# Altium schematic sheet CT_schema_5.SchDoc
size 255 x 245 mm
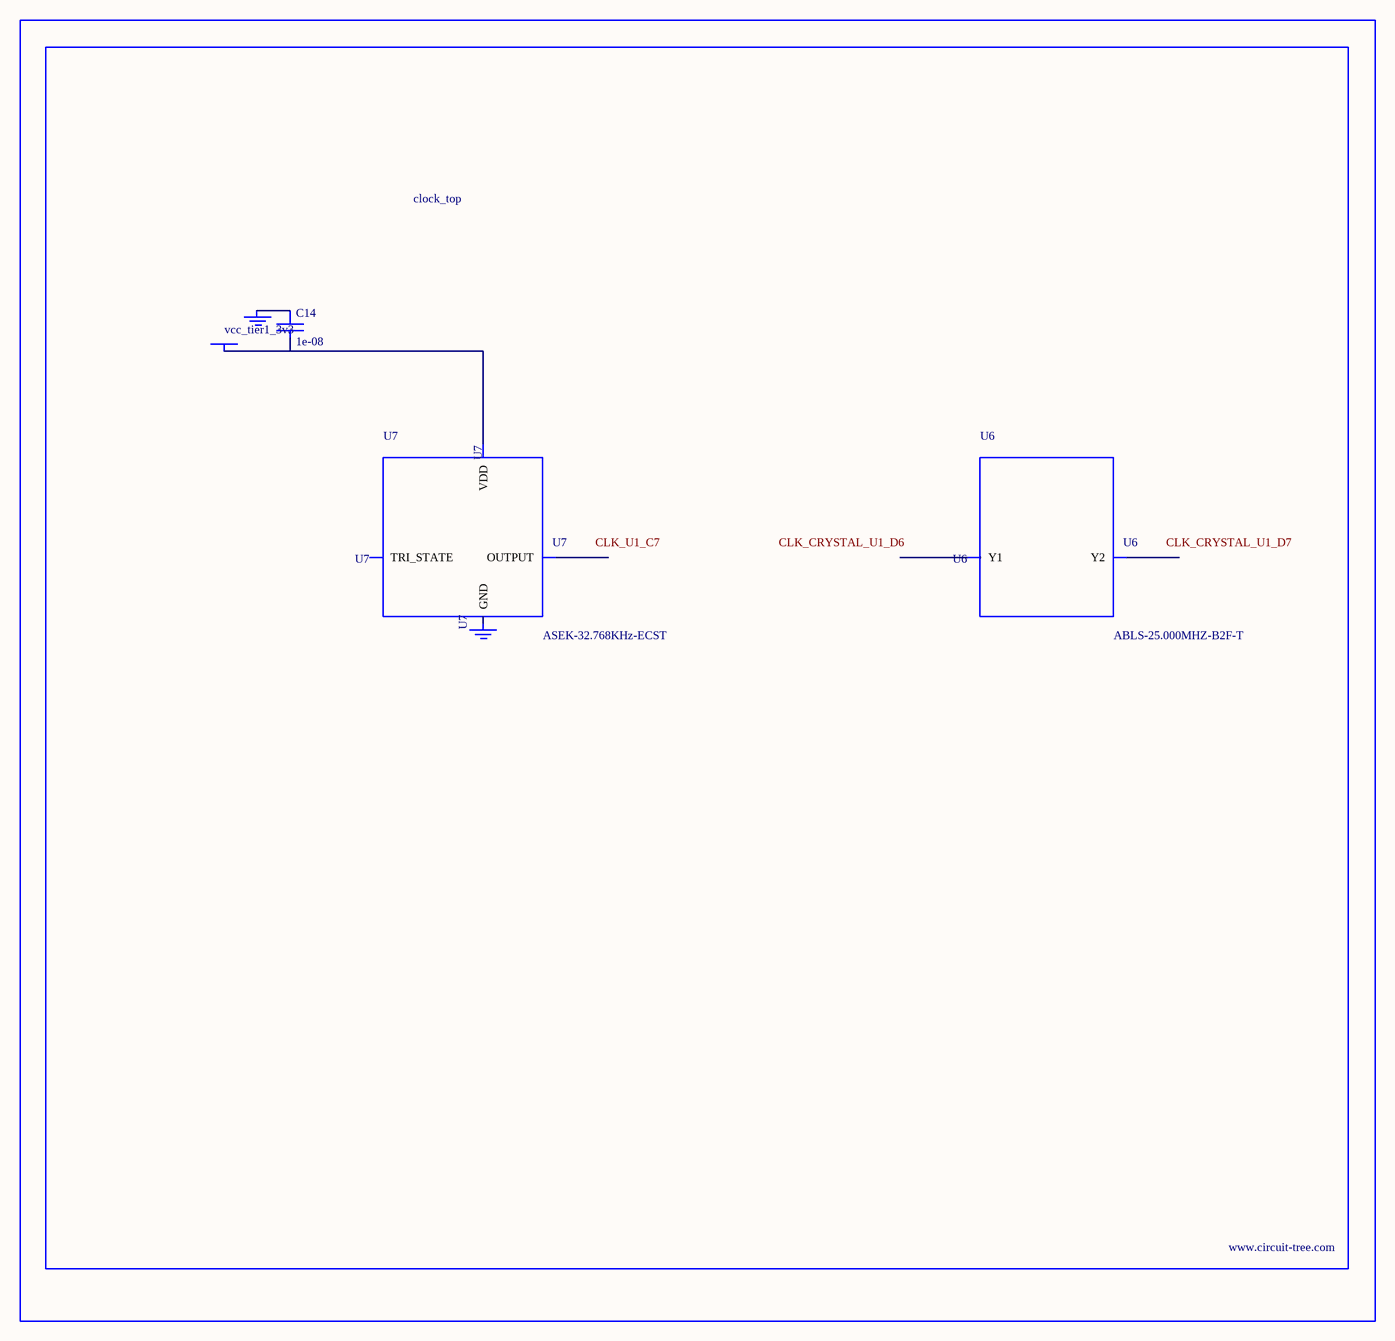
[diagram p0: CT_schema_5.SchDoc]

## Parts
BORDER4  (no value)
C14  1e-08  [C0402]
GND_INSTANCE_4_0  (no value)
GND_INSTANCE_4_1  (no value)
POWER_INSTANCE_4_0  vcc_tier1_3v3
U6  ABLS-25.000MHZ-B2F-T  [ABLS-25.000MHZ-B2F-T]
U7  ASEK-32.768KHz-ECST  [ASEK]

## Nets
NetC14_1: C14.1 GND_INSTANCE_4_0.0(GND)
NetC14_2: C14.2 POWER_INSTANCE_4_0.0(PWR) U7.4(VDD)

Not connected (* = marked no-connect by the designer): GND_INSTANCE_4_1 0(GND); U6 1(Y1) 2(Y2); U7 1(TRI_STATE) 2(GND) 3(OUTPUT)

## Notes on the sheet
- Labels drawn without touching a wire or pin: CLK_CRYSTAL_U1_D6, CLK_CRYSTAL_U1_D7, CLK_U1_C7

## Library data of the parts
BORDER4 = BORDER_PAGE4
C14 = C0402C103K3RAC
GND_INSTANCE_4_0 GND_INSTANCE_4_1 = GND
POWER_INSTANCE_4_0 = PWR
